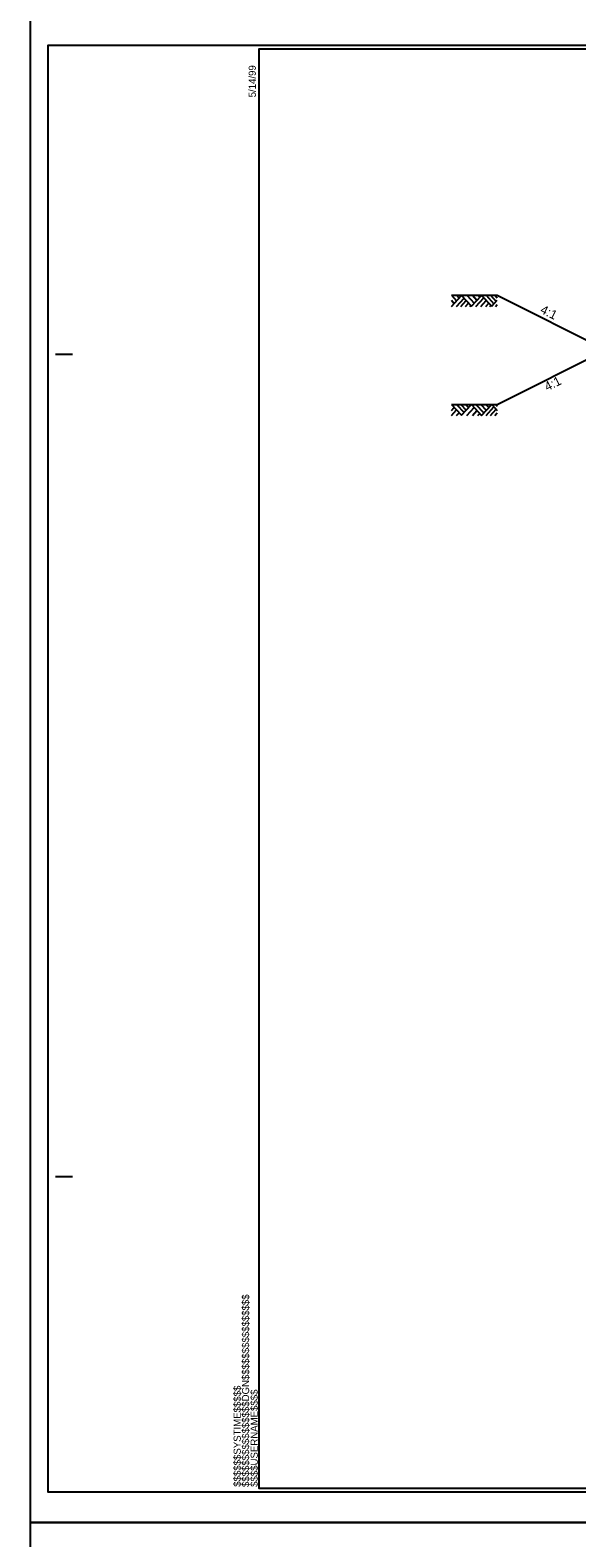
# Model space of a CAD drawing. Extents: x 1901670 to 1902225, y 193498 to 194278.
# Drawn here: x 1901965.8 to 1902005.8, y 193826.9 to 193936.9 of the extents above; entities that cross this region are included whole.
import ezdxf

# ---------------------------------------------------------------- set-up
doc = ezdxf.new("R2010")
doc.units = 0
for name, color, linetype in [('Old_Level_1', 7, 'Continuous'), ('Sheet Border Standard 30in CELL', 7, 'Continuous'), ('Sheet Cutting Line CELL', 7, 'Continuous'), ('Sheet Plot Border Inside CELL', 7, 'Continuous'), ('Sheet Plot Border Outside CELL', 7, 'Continuous'), ('Typical Pavement Slope CELL', 7, 'Continuous')]:
    doc.layers.add(name, color=color, linetype=linetype)

msp = doc.modelspace()

# ---------------------------------------------------------------- linework, layer by layer
at = {"layer": 'Old_Level_1'}
for p, q in [((1901996.6, 193917.55), (1901996.97, 193917.14)), ((1901996.6, 193916.74), (1901997.34, 193917.54)), ((1901996.6, 193917.18), (1901996.8, 193916.96)), ((1901996.97, 193917.55), (1901997.16, 193917.34)), ((1901996.97, 193916.74), (1901997.53, 193917.34)), ((1901997.28, 193916.74), (1901997.68, 193917.17)), ((1901997.34, 193917.54), (1901998.06, 193916.76)), ((1901997.63, 193916.74), (1901997.85, 193916.98)), ((1901997.73, 193917.55), (1901998.26, 193916.97)), ((1901997.94, 193916.74), (1901998.01, 193916.82)), ((1901998.06, 193916.76), (1901998.79, 193917.54)), ((1901998.13, 193917.55), (1901998.46, 193917.19)), ((1901998.37, 193916.74), (1901998.96, 193917.37)), ((1901998.53, 193917.55), (1901998.66, 193917.4)), ((1901998.74, 193916.74), (1901999.14, 193917.17)), ((1901998.79, 193917.54), (1901999.54, 193916.75)), ((1901999.11, 193916.74), (1901999.33, 193916.97)), ((1901999.12, 193917.55), (1901999.7, 193916.92)), ((1901999.4, 193916.74), (1901999.47, 193916.81)), ((1901999.45, 193917.55), (1901999.86, 193917.1)), ((1901999.54, 193916.75), (1901999.94, 193917.18)), ((1901999.77, 193917.55), (1901999.94, 193917.36)), ((1901999.81, 193916.74), (1901999.94, 193916.88)), ((1901996.6, 193909.59), (1901997.34, 193908.79)), ((1901996.6, 193909.15), (1901996.8, 193909.37)), ((1901996.6, 193908.78), (1901996.97, 193909.19)), ((1901996.97, 193909.59), (1901997.53, 193908.99)), ((1901997.28, 193909.59), (1901997.68, 193909.16)), ((1901997.34, 193908.79), (1901998.06, 193909.57)), ((1901997.63, 193909.59), (1901997.85, 193909.35)), ((1901997.73, 193908.78), (1901998.26, 193909.36)), ((1901997.94, 193909.59), (1901998.01, 193909.51)), ((1901998.06, 193909.57), (1901998.79, 193908.78)), ((1901998.13, 193908.78), (1901998.46, 193909.14)), ((1901998.37, 193909.59), (1901998.96, 193908.96)), ((1901998.74, 193909.59), (1901999.14, 193909.16)), ((1901998.79, 193908.78), (1901999.54, 193909.58)), ((1901999.11, 193909.59), (1901999.33, 193909.36)), ((1901999.12, 193908.78), (1901999.7, 193909.41)), ((1901999.4, 193909.59), (1901999.47, 193909.51)), ((1901999.45, 193908.78), (1901999.86, 193909.23)), ((1901999.54, 193909.58), (1901999.94, 193909.15)), ((1901999.81, 193909.59), (1901999.94, 193909.45)), ((1901996.97, 193908.78), (1901997.16, 193908.98)), ((1901998.53, 193908.78), (1901998.66, 193908.93)), ((1901999.77, 193908.78), (1901999.94, 193908.97))]:
    msp.add_line(p, q, dxfattribs=at)
at = {"layer": 'Sheet Border Standard 30in CELL'}
for p, q in [((1901982.64, 193935.51), (1901982.64, 193935.51)), ((1901967.69, 193913.26), (1901968.94, 193913.26)), ((1901967.69, 193853.26), (1901968.94, 193853.26))]:
    msp.add_line(p, q, dxfattribs=at)
msp.add_lwpolyline([(1902132.54, 193935.51), (1901982.54, 193935.51), (1901982.54, 193830.51), (1902132.54, 193830.51)], close=True, dxfattribs=at)
at = {"layer": 'Sheet Cutting Line CELL'}
for p, q in [((1901965.84, 193938.01), (1901965.84, 193828.01)), ((1901965.84, 193828.01), (1902134.24, 193828.01)), ((1902134.24, 193828.01), (1901965.84, 193828.01)), ((1901965.84, 193828.01), (1901965.84, 193718.01))]:
    msp.add_line(p, q, dxfattribs=at)
at = {"layer": 'Sheet Plot Border Inside CELL'}
msp.add_lwpolyline([(1902133.79, 193935.77), (1901967.14, 193935.77), (1901967.14, 193830.26), (1902133.79, 193830.26)], close=True, dxfattribs=at)
at = {"layer": 'Sheet Plot Border Outside CELL'}
for points in [[(1902134.24, 193938.01), (1901965.84, 193938.01), (1901965.84, 193828.01), (1902134.24, 193828.01)], [(1902134.24, 193828.01), (1901965.84, 193828.01), (1901965.84, 193718.01), (1902134.24, 193718.01)]]:
    msp.add_lwpolyline(points, close=True, dxfattribs=at)
at = {"layer": 'Typical Pavement Slope CELL'}
for p in [(1901999.94, 193917.55), (1901999.94, 193909.59)]:
    msp.add_line(p, (1902007.9, 193913.57), dxfattribs=at)
for points in [[(1901996.6, 193917.55), (1901999.94, 193917.55)], [(1901996.6, 193909.59), (1901999.94, 193909.59)]]:
    msp.add_lwpolyline(points, dxfattribs=at)

# ---------------------------------------------------------------- texts
at = {"layer": 'Old_Level_1'}
for rotation, p in [(333.4349, (1902003.02, 193916.29)), (26.5651, (1902003.59, 193910.54))]:
    msp.add_text('4:1', height=0.656, rotation=rotation, dxfattribs=at).set_placement(p)
at = {"layer": 'Sheet Border Standard 30in CELL'}
for s, p in [('5/14/99', (1901982.32, 193931.99)), ('$$$$$$$$$$$$$$$$DGN$$$$$$$$$$$$$$$$', (1901981.83, 193830.6)), ('$$$$$$SYSTIME$$$$$', (1901981.22, 193830.62)), ('$$$$USERNAME$$$$', (1901982.46, 193830.61))]:
    msp.add_text(s, height=0.525, rotation=90, dxfattribs=at).set_placement(p)

doc.saveas('drawing.dxf')
